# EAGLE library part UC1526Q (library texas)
PULSE WIDTH MODULATOR
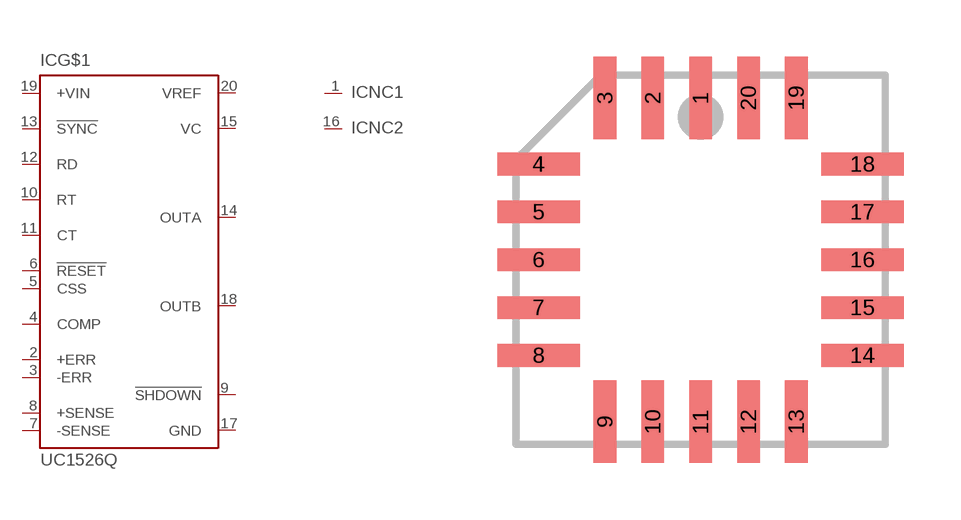
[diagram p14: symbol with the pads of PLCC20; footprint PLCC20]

Designator prefix IC; gates G$1=UC1526 NC1=NC NC2=NC

## UC1526Q (OC_FARNELL: unknown; OC_NEWARK: unknown)  [PLCC20]
1  NC1:NC  nc
2  G$1:+ERR  in
3  G$1:-ERR  in
4  G$1:COMP  pas
5  G$1:CSS  in
6  G$1:!RESET  in
7  G$1:-SENSE  in
8  G$1:+SENSE  in
9  G$1:!SHDOWN  out
10  G$1:RT  pas
11  G$1:CT  pas
12  G$1:RD  pas
13  G$1:!SYNC  in
14  G$1:OUTA  out
15  G$1:VC  in
16  NC2:NC  nc
17  G$1:GND  pwr
18  G$1:OUTB  out
19  G$1:+VIN  in
20  G$1:VREF  out

## Footprint PLCC20 (pad centres in mm)
Plastic Leaded Chip Carrier
smd 0.6 x 2.2: 1 0,4.3; 2 -1.27,4.3; 3 -2.54,4.3; 9 -2.54,-4.3; 10 -1.27,-4.3; 11 0,-4.3; 12 1.27,-4.3; 13 2.54,-4.3; 19 2.54,4.3; 20 1.27,4.3
smd 2.2 x 0.6: 4 -4.3,2.54; 5 -4.3,1.27; 6 -4.3,0; 7 -4.3,-1.27; 8 -4.3,-2.54; 14 4.3,-2.54; 15 4.3,-1.27; 16 4.3,0; 17 4.3,1.27; 18 4.3,2.54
